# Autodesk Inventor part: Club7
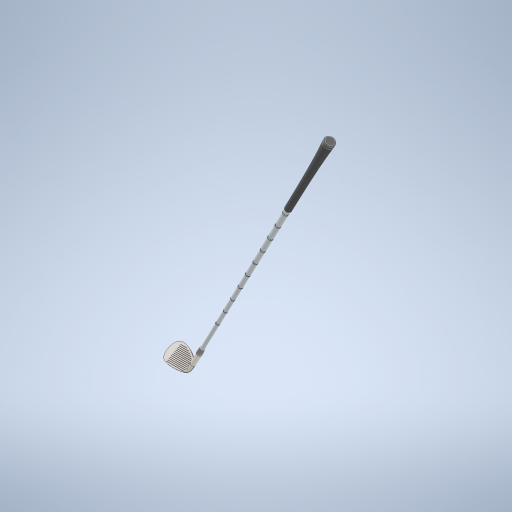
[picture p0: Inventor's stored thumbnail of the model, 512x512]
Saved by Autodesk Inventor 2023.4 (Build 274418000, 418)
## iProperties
Created: 2012-07
Part Number: Club7
Material: Générique
Document SubType Name: Modeling
Designer: bruno
Density: 1 g/cm^3
Appearance: Par défaut
Author: bruno
Sending System: SolidWorks 2011
Last Author: Steen
Last Saved: 2012-07-11
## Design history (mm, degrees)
node "Spalding 62 degree wedge.SLDPRT"
node "Solide1"
feature "Spalding 62degree v2-1-solid1"
node "Solide2"
feature "Shaft-1-solid1"
node "Solide3"
feature "Ferrule-1-solid1"
node "Solide4"
feature "Grip-1-solid1"
